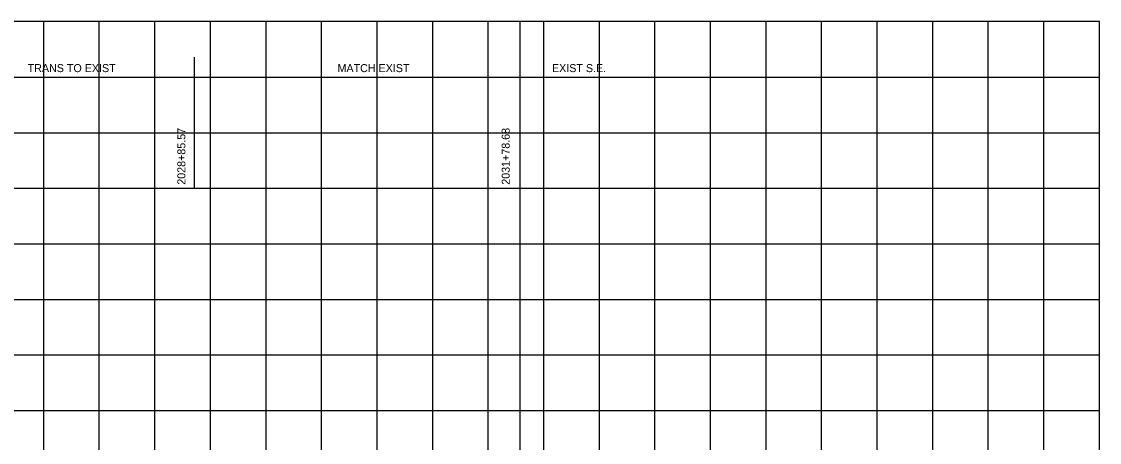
# Model space of a CAD drawing. Extents: x -7164 to 2214450, y -19642 to 253469.
# Drawn here: x 8730 to 9700, y 621 to 1000 of the extents above; entities that cross this region are included whole.
import ezdxf

# ---------------------------------------------------------------- set-up
doc = ezdxf.new("R2010")
doc.units = 0
for name, color, linetype in [('DESIGN - PROFILE - Proposed Curve Text', 7, 'Continuous'), ('DESIGN - SCRATCH - User 1', 7, 'Continuous'), ('DESIGN - SHEET - Light Grid', 7, 'Continuous')]:
    doc.layers.add(name, color=color, linetype=linetype)

msp = doc.modelspace()

# ---------------------------------------------------------------- linework, layer by layer
at = {"layer": 'DESIGN - PROFILE - Proposed Curve Text'}
for p, q in [((8885.57, 850), (8885.57, 968.1)), ((8885.57, 850), (8885.57, 968.1)), ((9178.68, 850), (9178.68, 968.1)), ((9178.68, 850), (9178.68, 968.1)), ((8663.35, 950), (8885.57, 950)), ((8663.35, 950), (8885.57, 950)), ((8885.57, 950), (9178.68, 950)), ((8885.57, 950), (9178.68, 950)), ((9178.68, 950), (9700, 950)), ((9178.68, 950), (9700, 950))]:
    msp.add_line(p, q, dxfattribs=at)
at = {"layer": 'DESIGN - SCRATCH - User 1'}
for p, q in [((9700, 1000), (6000, 1000)), ((9700, 1000), (6000, 1000)), ((9700, 0), (9700, 1000)), ((9700, 0), (9700, 1000))]:
    msp.add_line(p, q, dxfattribs=at)
msp.add_lwpolyline([(6000, 0), (9178.68, 0), (9178.68, 1000)], dxfattribs=at)
msp.add_lwpolyline([(6000, 0), (9178.68, 0), (9178.68, 1000)], dxfattribs=at)
at = {"layer": 'DESIGN - SHEET - Light Grid'}
for p, q in [((8750, 0), (8750, 1000)), ((8750, 0), (8750, 1000)), ((8800, 0), (8800, 1000)), ((8800, 0), (8800, 1000)), ((8850, 0), (8850, 1000)), ((8850, 0), (8850, 1000)), ((8900, 0), (8900, 1000)), ((8900, 0), (8900, 1000)), ((8950, 0), (8950, 1000)), ((8950, 0), (8950, 1000)), ((9000, 0), (9000, 1000)), ((9000, 0), (9000, 1000)), ((9050, 0), (9050, 1000)), ((9050, 0), (9050, 1000)), ((9100, 0), (9100, 1000)), ((9100, 0), (9100, 1000)), ((9150, 0), (9150, 1000)), ((9150, 0), (9150, 1000)), ((9200, 0), (9200, 1000)), ((9200, 0), (9200, 1000)), ((9250, 0), (9250, 1000)), ((9250, 0), (9250, 1000)), ((9300, 0), (9300, 1000)), ((9300, 0), (9300, 1000)), ((9350, 0), (9350, 1000)), ((9350, 0), (9350, 1000)), ((9400, 0), (9400, 1000)), ((9400, 0), (9400, 1000)), ((9450, 0), (9450, 1000)), ((9450, 0), (9450, 1000)), ((9500, 0), (9500, 1000)), ((9500, 0), (9500, 1000)), ((9550, 0), (9550, 1000)), ((9550, 0), (9550, 1000)), ((9600, 0), (9600, 1000)), ((9600, 0), (9600, 1000)), ((9650, 0), (9650, 1000)), ((9650, 0), (9650, 1000)), ((6000, 950), (9700, 950)), ((6000, 950), (9700, 950)), ((6000, 900), (9700, 900)), ((6000, 900), (9700, 900)), ((6000, 850), (9700, 850)), ((6000, 850), (9700, 850)), ((6000, 800), (9700, 800)), ((6000, 800), (9700, 800)), ((6000, 750), (9700, 750)), ((6000, 750), (9700, 750)), ((6000, 700), (9700, 700)), ((6000, 700), (9700, 700)), ((6000, 650), (9700, 650)), ((6000, 650), (9700, 650))]:
    msp.add_line(p, q, dxfattribs=at)

# ---------------------------------------------------------------- texts
at = {"layer": 'DESIGN - PROFILE - Proposed Curve Text'}
for s, p in [('TRANS TO EXIST', (8735.54, 954.51)), ('MATCH EXIST', (9014.39, 954.51)), ('EXIST S.E.', (9207.37, 954.51))]:
    msp.add_text(s, height=7.2, dxfattribs=at).set_placement(p)
for s, rotation, p in [('TRANS TO EXIST', 360, (8735.54, 954.51)), ('MATCH EXIST', 360, (9014.39, 954.51)), ('EXIST S.E.', 360, (9207.37, 954.51)), ('2028+85.57', 90, (8877.44, 853.16)), ('2028+85.57', 90, (8877.44, 853.16)), ('2031+78.68', 90, (9169.31, 853.16)), ('2031+78.68', 90, (9169.31, 853.16))]:
    msp.add_text(s, height=7.2, rotation=rotation, dxfattribs=at).set_placement(p)

doc.saveas('drawing.dxf')
